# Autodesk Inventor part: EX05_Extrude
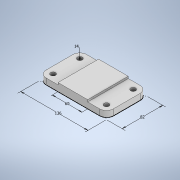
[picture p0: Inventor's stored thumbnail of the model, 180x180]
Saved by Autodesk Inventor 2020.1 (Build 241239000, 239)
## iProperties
Created: 2019-10
Part Number: EX05_Extrude
Material: Generic
Document SubType Name: Modeling
Designer: Synergysoft Dell02
Density: 1 g/cm^3
Appearance: Default
Author: Synergysoft Dell02
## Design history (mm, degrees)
sketch "Sketch1"
  geometry: L1 (54, -41)-(-54, -41); L2 (-68, -27)-(-68, 27); L3 (-54, 41)-(54, 41); L4 (68, 27)-(68, -27); L5 (68, -41)-(-68, 41); L6 (-68, -41)-(68, 41); L7 (30, -41)-(-30, -41); L8 (-30, -41)-(-30, 41); L9 (-30, 41)-(30, 41); L10 (30, 41)-(30, -41); L11 (30, -41)-(-30, 41); L12 (-30, -41)-(30, 41); A1 r 14 centre (54, -27) between (54, -41) and (68, -27); A2 r 14 centre (-54, -27) between (-68, -27) and (-54, -41); A3 r 14 centre (-54, 27) between (-54, 41) and (-68, 27); A4 r 14 centre (54, 27) between (68, 27) and (54, 41); 4 further points
  constraints: 24 end point, 9 point on line, 8 point on circle, 8 tangent, 4 centre point, 4 midpoint, 4 parallel, 3 equal radius, 2 horizontal, 2 perpendicular
  dimensions: "d0" = 136 distance of L5.end L6.end; "d1" = 82 distance of L6.start L5.end; "d2" = 60 distance of L8.end L9.end; "d3" = 14 radius of A1
extrude "Extrusion1" new body sketch "Sketch1" distance "d4" = 12; taper "d5" = 0 deg
extrude "Extrusion2" join sketch "Sketch1" distance "d6" = 16; taper "d7" = 0 deg
body "Solid1"
sketch "Sketch2"
  geometry: L1 (-68, 27)-(-68, -27) reference; L2 (-30, 41)-(-54, 41) reference; C1 r 5 at (-54, 27); C2 r 5 at (54, 27); C3 r 5 at (-54, -27); C4 r 5 at (54, -27); 1 further point
  constraints: 4 centre point, 1 horizontal, 1 vertical, 6 other
  dimensions: "d8" = 10 diameter of C1; "d9" = 14 distance from line of C1.centre L1; "d10" = 14 distance from line of L2 C1.centre; "d13" = 108 distance of C1.centre C2.centre; "d16" = 54 distance of C1.centre C3.centre
extrude "Extrusion3" cut sketch "Sketch2" distance "d21" = 12; taper "d22" = 0 deg
